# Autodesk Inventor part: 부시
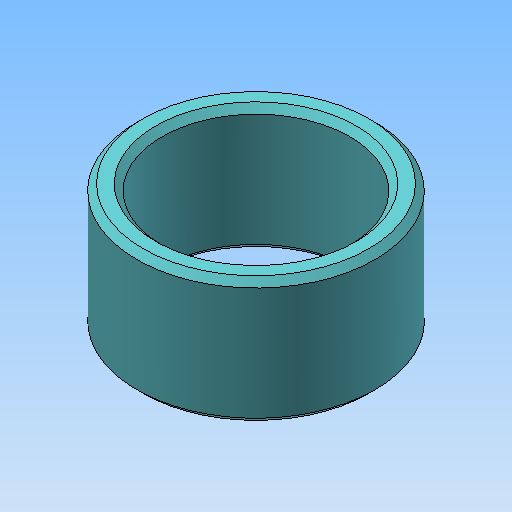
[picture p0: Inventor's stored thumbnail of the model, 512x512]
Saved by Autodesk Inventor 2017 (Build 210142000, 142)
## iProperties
Created: 2013-01
Part Number: 부시
Document SubType Name: Modeling
Designer: mdu
Density: 1 g/cm^3
Material: 강철, 연강
Appearance: 하늘색 중간
Author: mdu
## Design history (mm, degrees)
sketch "스케치1"
  geometry: L1 (15, 20)-(15, -46) reference; L2 (-20, 19)-(20, 19); L3 (30.7, -1)-(-30.7, -1) reference; L4 (19, 19)-(19, -1); L5 (15, -1)-(19, -1); L6 (0, 0)-(0, 19); L7 (19, 19)-(15, 19)
  constraints: 12 end point, 6 point on line, 1 collinear, 1 midpoint, 1 perpendicular, 1 vertical, 2 other
  dimensions: "d0" = 38 diameter of L4 L6; "d5" = 20 distance between parallel lines of L2 L3
revolve "회전1" sketch "스케치1" stored, may be unused: angle "d1" = 90 deg
chamfer "모따기1" distance "d2" = 1; stored, may be unused: second distance "d3" = 2, angle "d4" = 45 deg
node "솔리드1"
node "참조2"
